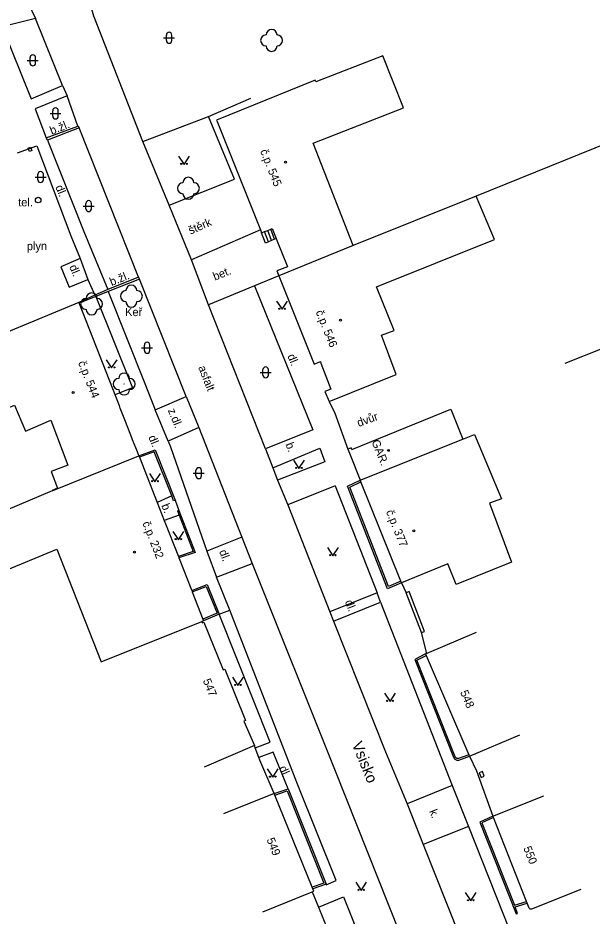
# Model space of a CAD drawing. Extents: x -577457 to -568404, y -1208466 to -1201387.
# Drawn here: x -575093.5 to -575041.2, y -1204524.1 to -1204442.2 of the extents above; entities that cross this region are included whole.
import ezdxf

# ---------------------------------------------------------------- set-up
doc = ezdxf.new("R2010")
doc.units = 0
for name, color, linetype in [('BUDOVY_MĚŘ', 7, 'Continuous'), ('BUDOVY_NEMĚŘ', 7, 'Continuous'), ('NÁZVY_ULIC_TOK_SMĚR', 7, 'Continuous'), ('OBVOD_PILÍŘE', 7, 'Continuous'), ('POMOC_POPIS', 7, 'Continuous'), ('ROZHRANÍ_PLOCH', 7, 'Continuous'), ('ZELEŇ', 7, 'Continuous'), ('ZN_BUDOV', 7, 'Continuous'), ('ZN_DOPLŇKOVÉ', 7, 'Continuous'), ('ZN_KULTUR', 7, 'Continuous'), ('Č_POPIS_ORIENT', 7, 'Continuous')]:
    doc.layers.add(name, color=color, linetype=linetype)

msp = doc.modelspace()

# ---------------------------------------------------------------- linework, layer by layer
at = {"layer": 'BUDOVY_MĚŘ'}
for points in [[(-575075.44, -1204451.53), (-575075.38, -1204451.68)], [(-575075.38, -1204451.68), (-575071.43, -1204461.55), (-575071.36, -1204461.73)], [(-575071.36, -1204461.73), (-575071.33, -1204461.81)], [(-575071.33, -1204461.81), (-575071.05, -1204461.7)], [(-575071.05, -1204461.7), (-575070.77, -1204461.59)], [(-575070.77, -1204461.59), (-575070.5, -1204461.48)], [(-575070.5, -1204461.48), (-575070.37, -1204461.43)], [(-575070.01, -1204462.33), (-575069.91, -1204462.58)], [(-575068.99, -1204464.84), (-575068.96, -1204464.92), (-575069.93, -1204465.28), (-575069.76, -1204465.75)], [(-575069.76, -1204465.75), (-575069.71, -1204465.88)], [(-575069.71, -1204465.88), (-575066.65, -1204473.49)], [(-575087.98, -1204468.17), (-575087.95, -1204468.25)], [(-575087.95, -1204468.25), (-575084.33, -1204477.56)], [(-575066.65, -1204473.49), (-575066.59, -1204473.63)], [(-575066.59, -1204473.63), (-575066.53, -1204473.79), (-575065.97, -1204473.56), (-575065.92, -1204473.7)], [(-575065.61, -1204474.49), (-575065, -1204476.06), (-575065.55, -1204476.29), (-575065.18, -1204477.2)], [(-575084.33, -1204477.56), (-575084.27, -1204477.72)], [(-575084.27, -1204477.72), (-575084.25, -1204477.77)], [(-575083.77, -1204479), (-575083.18, -1204480.49)], [(-575083.18, -1204480.49), (-575083.12, -1204480.65)], [(-575083.12, -1204480.65), (-575082.67, -1204481.77)], [(-575063.1, -1204481.56), (-575063.15, -1204481.42), (-575063.47, -1204481.53)], [(-575063.47, -1204481.53), (-575063.26, -1204482.05)], [(-575082.67, -1204481.77), (-575082.61, -1204481.93)], [(-575082.61, -1204481.93), (-575082.52, -1204482.15)], [(-575082.52, -1204482.15), (-575082.47, -1204482.28)], [(-575082.47, -1204482.28), (-575080.85, -1204486.39)], [(-575062.37, -1204484.27), (-575062.33, -1204484.37)], [(-575062.27, -1204484.51), (-575062.33, -1204484.37)], [(-575058.62, -1204493.57), (-575062.27, -1204484.51)], [(-575080.85, -1204486.39), (-575080.2, -1204488.04)], [(-575080.2, -1204488.04), (-575078.91, -1204491.33)], [(-575078.91, -1204491.33), (-575078.86, -1204491.46)], [(-575078.86, -1204491.46), (-575078.79, -1204491.65)], [(-575058.56, -1204493.72), (-575058.62, -1204493.57)], [(-575077.78, -1204494.23), (-575077.7, -1204494.42)], [(-575077.7, -1204494.42), (-575077.65, -1204494.56)], [(-575077.65, -1204494.56), (-575076.68, -1204497.04)], [(-575076.68, -1204497.04), (-575076.62, -1204497.18)], [(-575076.62, -1204497.18), (-575076.79, -1204497.25)], [(-575076.79, -1204497.25), (-575076.74, -1204497.38), (-575076.6, -1204497.32), (-575074.83, -1204501.65), (-575074.69, -1204501.6), (-575072.8, -1204506.27), (-575072.94, -1204506.33), (-575071.98, -1204508.57)], [(-575051.77, -1204498.25), (-575056.25, -1204500.16)], [(-575056.25, -1204500.16), (-575056.37, -1204500.21)], [(-575056.37, -1204500.21), (-575056.31, -1204500.35)], [(-575056.31, -1204500.35), (-575052.44, -1204509.4)], [(-575052.38, -1204509.54), (-575047.79, -1204507.58)], [(-575071.98, -1204508.57), (-575076.58, -1204510.54)], [(-575052.44, -1204509.4), (-575052.38, -1204509.54)], [(-575070.17, -1204512.93), (-575074.81, -1204514.8)], [(-575070.11, -1204513.08), (-575070.17, -1204512.93)], [(-575066.72, -1204521.48), (-575070.11, -1204513.08)], [(-575050.24, -1204515), (-575045.59, -1204513.16)], [(-575050.18, -1204515.14), (-575050.24, -1204515)], [(-575047.17, -1204522.79), (-575050.18, -1204515.14)], [(-575066.66, -1204521.63), (-575066.72, -1204521.48)], [(-575066.72, -1204521.91), (-575066.57, -1204521.85), (-575066.66, -1204521.63)], [(-575042.22, -1204521.7), (-575046.73, -1204523.48), (-575046.84, -1204523.48), (-575046.93, -1204523.4), (-575047.11, -1204522.93)], [(-575071.21, -1204523.72), (-575066.72, -1204521.91)], [(-575047.11, -1204522.93), (-575047.17, -1204522.79)]]:
    msp.add_lwpolyline(points, dxfattribs=at)
at = {"layer": 'BUDOVY_NEMĚŘ'}
for points in [[(-575062.99, -1204462.97), (-575066.63, -1204453.64), (-575058.38, -1204450.42), (-575060.28, -1204445.68), (-575066.38, -1204448.06), (-575066.44, -1204447.91), (-575075.44, -1204451.53)], [(-575065.18, -1204477.2), (-575059.05, -1204474.73), (-575060.4, -1204471.16), (-575059.24, -1204470.72), (-575060.84, -1204466.73), (-575050.1, -1204462.42), (-575051.77, -1204458.47), (-575062.99, -1204462.97), (-575069.76, -1204465.75)], [(-575087.98, -1204468.17), (-575098.86, -1204472.68), (-575102.69, -1204474.2), (-575109.74, -1204477.23), (-575108, -1204481.48), (-575098.52, -1204477.5), (-575097.81, -1204479.2), (-575093.85, -1204477.52), (-575092.85, -1204479.89), (-575090.54, -1204478.91), (-575089.01, -1204483), (-575090.52, -1204483.58), (-575089.95, -1204485.11), (-575090.43, -1204485.3), (-575090.41, -1204485.35), (-575082.52, -1204482.15)], [(-575063.1, -1204481.56), (-575054.08, -1204477.88), (-575052.98, -1204480.63)], [(-575062.33, -1204484.37), (-575052.98, -1204480.63), (-575051.9, -1204480.2), (-575049.46, -1204486.06), (-575050.56, -1204486.47), (-575048.55, -1204491.85), (-575053.58, -1204493.88), (-575054.34, -1204492.01), (-575058.56, -1204493.72)], [(-575090.41, -1204485.35), (-575099.9, -1204489.34), (-575103.91, -1204491.03), (-575109.16, -1204493.23), (-575107.19, -1204497.79), (-575098.59, -1204494.23), (-575089.99, -1204490.66), (-575085.95, -1204500.94), (-575076.79, -1204497.25)]]:
    msp.add_lwpolyline(points, dxfattribs=at)
at = {"layer": 'OBVOD_PILÍŘE'}
msp.add_lwpolyline([(-575092.34, -1204454.17), (-575092.28, -1204454.32), (-575092.49, -1204454.4), (-575092.6, -1204454.1), (-575092.4, -1204454.02), (-575092.34, -1204454.17)], dxfattribs=at)
at = {"layer": 'ROZHRANÍ_PLOCH'}
for points in [[(-575082.17, -1204453.5), (-575086.64, -1204442.06), (-575086.9, -1204441.13), (-575085.27, -1204440.74), (-575085.33, -1204439.77), (-575085.22, -1204438.76), (-575085.08, -1204438.35), (-575084.56, -1204437.58), (-575084.14, -1204437.25), (-575083.73, -1204436.91), (-575082.75, -1204436.68), (-575075.88, -1204435.68), (-575075.55, -1204437.94), (-575072.53, -1204437.47)], [(-575093.33, -1204439.52), (-575092.57, -1204440.95), (-575091.95, -1204442.28)], [(-575091.95, -1204442.28), (-575094.97, -1204443.02), (-575092.34, -1204449.59), (-575089.47, -1204448.38)], [(-575089.47, -1204448.38), (-575091.95, -1204442.28)], [(-575089.47, -1204448.38), (-575089.06, -1204449.34)], [(-575089.06, -1204449.34), (-575091.97, -1204450.51), (-575090.98, -1204453.17)], [(-575088.08, -1204452.08), (-575089.06, -1204449.34)], [(-575079.76, -1204459.29), (-575073.79, -1204456.93), (-575076.18, -1204451.2), (-575072.3, -1204449.55)], [(-575082.54, -1204465.87), (-575087.97, -1204452.25)], [(-575090.84, -1204453.37), (-575087.55, -1204461.69), (-575085.35, -1204466.97)], [(-575079.76, -1204459.29), (-575082.17, -1204453.5)], [(-575093.58, -1204454.52), (-575091.83, -1204453.89), (-575088.73, -1204462.08), (-575087.88, -1204464.15), (-575089.62, -1204464.93), (-575088.87, -1204466.77), (-575087.18, -1204466.07), (-575086.54, -1204467.49)], [(-575071.43, -1204461.55), (-575077.71, -1204464.27), (-575079.76, -1204459.29)], [(-575070.7, -1204462.63), (-575070.98, -1204462.75), (-575071.33, -1204461.81)], [(-575070.7, -1204462.63), (-575071.05, -1204461.7)], [(-575070.43, -1204462.51), (-575070.77, -1204461.59)], [(-575070.15, -1204462.39), (-575070.5, -1204461.48)], [(-575070.43, -1204462.51), (-575070.7, -1204462.63)], [(-575070.15, -1204462.39), (-575070.43, -1204462.51)], [(-575070.01, -1204462.33), (-575070.15, -1204462.39)], [(-575087.88, -1204464.15), (-575087.18, -1204466.07)], [(-575076.16, -1204468.38), (-575077.71, -1204464.27)], [(-575078.22, -1204476.75), (-575082.45, -1204466.03)], [(-575071.97, -1204466.66), (-575076.16, -1204468.38)], [(-575071.97, -1204466.66), (-575066.66, -1204479.77), (-575070.97, -1204481.5)], [(-575086.43, -1204467.61), (-575083.1, -1204475.96), (-575084.7, -1204476.59)], [(-575085.33, -1204467.17), (-575081.96, -1204475.54), (-575081.03, -1204477.95), (-575078.22, -1204476.75)], [(-575070.97, -1204481.5), (-575076.16, -1204468.38)], [(-575078.22, -1204476.75), (-575077.06, -1204479.57)], [(-575079.85, -1204480.81), (-575081.03, -1204477.95)], [(-575077.06, -1204479.57), (-575079.85, -1204480.81), (-575079.63, -1204481.33)], [(-575077.06, -1204479.57), (-575073.13, -1204489.58)], [(-575079.63, -1204481.33), (-575076.31, -1204490.85)], [(-575070.97, -1204481.5), (-575070.31, -1204483.23)], [(-575070.31, -1204483.23), (-575066.01, -1204481.45), (-575065.56, -1204482.69)], [(-575065.56, -1204482.69), (-575069.88, -1204484.36)], [(-575070.31, -1204483.23), (-575069.88, -1204484.36)], [(-575069.88, -1204484.36), (-575068.95, -1204486.61)], [(-575064.61, -1204484.88), (-575068.95, -1204486.61)], [(-575064.61, -1204484.88), (-575060.79, -1204494.65)], [(-575079.52, -1204485.8), (-575080.85, -1204486.39)], [(-575068.95, -1204486.61), (-575065.1, -1204496.36)], [(-575078.85, -1204487.55), (-575080.2, -1204488.04)], [(-575073.13, -1204489.58), (-575076.31, -1204490.85)], [(-575073.13, -1204489.58), (-575072.18, -1204491.97)], [(-575076.31, -1204490.85), (-575075.44, -1204493.21)], [(-575075.44, -1204493.21), (-575072.18, -1204491.97)], [(-575072.18, -1204491.97), (-575064.62, -1204510.86), (-575052.9, -1204540.39)], [(-575074.21, -1204496.22), (-575075.44, -1204493.21)], [(-575060.79, -1204494.65), (-575065.1, -1204496.36)], [(-575060.49, -1204495.49), (-575060.79, -1204494.65)], [(-575064.77, -1204497.21), (-575060.49, -1204495.49)], [(-575060.49, -1204495.49), (-575053.94, -1204512.22)], [(-575075.19, -1204496.58), (-575074.21, -1204496.22)], [(-575065.45, -1204521.21), (-575065.43, -1204521.27), (-575064.52, -1204520.86), (-575068.04, -1204512.1), (-575074.21, -1204496.22)], [(-575071.91, -1204508.76), (-575070.56, -1204508.25), (-575075.19, -1204496.58)], [(-575065.1, -1204496.36), (-575064.77, -1204497.21)], [(-575064.77, -1204497.21), (-575060.04, -1204509.13), (-575058.07, -1204513.88)], [(-575068.9, -1204512.51), (-575070.26, -1204509.18), (-575071.58, -1204509.66)], [(-575053.94, -1204512.22), (-575058.07, -1204513.88)], [(-575053.94, -1204512.22), (-575052.47, -1204515.95)], [(-575058.07, -1204513.88), (-575056.59, -1204517.59)], [(-575052.47, -1204515.95), (-575056.59, -1204517.59)], [(-575052.47, -1204515.95), (-575048.12, -1204526.92)], [(-575056.59, -1204517.59), (-575052.21, -1204528.58)], [(-575066.15, -1204523.31), (-575063.85, -1204522.37), (-575058.31, -1204536.3), (-575058.02, -1204536.17), (-575055.71, -1204541.56), (-575056.12, -1204541.74), (-575055.95, -1204542.22)]]:
    msp.add_lwpolyline(points, dxfattribs=at)
at = {"layer": 'ZELEŇ'}
msp.add_lwpolyline([(-575082.17, -1204453.5), (-575076.18, -1204451.2)], dxfattribs=at)
for centre in [(-575070.42, -1204444.27), (-575078, -1204457.75), (-575083.2, -1204467.59), (-575086.83, -1204468.3), (-575083.86, -1204475.6)]:
    msp.add_circle(centre, 0.0005, dxfattribs=at)
for centre, start, end in [((-575070.92, -1204444.27), 89.99999, 269.99999), ((-575070.42, -1204443.77), 0, 179.99999), ((-575069.92, -1204444.27), 270, 89.99999), ((-575070.42, -1204444.77), 179.99999, 359.99999), ((-575078, -1204457.25), 0, 179.99999), ((-575078.5, -1204457.75), 89.99999, 269.99999), ((-575077.5, -1204457.75), 270, 89.99999), ((-575078, -1204458.25), 179.99999, 359.99999), ((-575083.2, -1204467.09), 0, 179.99999), ((-575086.83, -1204467.8), 0, 179.99999), ((-575083.7, -1204467.59), 89.99999, 269.99999), ((-575082.7, -1204467.59), 270, 89.99999), ((-575087.33, -1204468.3), 89.99999, 269.99999), ((-575086.33, -1204468.3), 270, 89.99999), ((-575083.2, -1204468.09), 179.99999, 359.99999), ((-575086.83, -1204468.8), 179.99999, 359.99999), ((-575083.86, -1204475.1), 0, 179.99999), ((-575084.36, -1204475.6), 89.99999, 269.99999), ((-575083.36, -1204475.6), 270, 89.99999), ((-575083.86, -1204476.1), 179.99999, 359.99999)]:
    msp.add_arc(centre, 0.5, start, end, dxfattribs=at)
at = {"layer": 'ZN_BUDOV'}
for centre in [(-575069.16, -1204455.38), (-575064.13, -1204469.77), (-575088.5, -1204476.38), (-575059.77, -1204481.65), (-575057.45, -1204488.98), (-575082.93, -1204490.94)]:
    msp.add_circle(centre, 0.0875, dxfattribs=at)
at = {"layer": 'ZN_DOPLŇKOVÉ'}
for points in [[(-575014.05, -1204443.22), (-575051.77, -1204458.47)], [(-575090.98, -1204453.17), (-575088.08, -1204452.08), (-575087.97, -1204452.25), (-575090.84, -1204453.37), (-575090.98, -1204453.17)], [(-575007.73, -1204459.47), (-575043.68, -1204473.72)], [(-575070.37, -1204461.43), (-575070.01, -1204462.33)], [(-575069.91, -1204462.58), (-575068.99, -1204464.84)], [(-575082.54, -1204465.87), (-575085.35, -1204466.97), (-575086.54, -1204467.49), (-575087.98, -1204468.17)], [(-575082.54, -1204465.87), (-575082.45, -1204466.03), (-575085.33, -1204467.17), (-575086.43, -1204467.61), (-575087.52, -1204468.06), (-575087.95, -1204468.25)], [(-575069.76, -1204465.75), (-575071.97, -1204466.66)], [(-575065.92, -1204473.7), (-575065.61, -1204474.49)], [(-575065.18, -1204477.2), (-575064.64, -1204478.27), (-575063.47, -1204481.53)], [(-575084.25, -1204477.77), (-575083.77, -1204479)], [(-575082.52, -1204482.15), (-575081.04, -1204481.61), (-575079.22, -1204486.19)], [(-575079.52, -1204485.8), (-575081.12, -1204481.79), (-575082.47, -1204482.28)], [(-575063.26, -1204482.05), (-575062.37, -1204484.27)], [(-575058.56, -1204493.72), (-575059.86, -1204494.27), (-575063.5, -1204484.93), (-575062.33, -1204484.37)], [(-575058.62, -1204493.57), (-575059.77, -1204494.06), (-575063.29, -1204485.01), (-575062.27, -1204484.51)], [(-575079.22, -1204486.19), (-575079.35, -1204486.24), (-575079.52, -1204485.8)], [(-575079.22, -1204486.19), (-575078.86, -1204487.13)], [(-575078.86, -1204487.13), (-575078.99, -1204487.18), (-575078.85, -1204487.55)], [(-575078.86, -1204487.13), (-575077.39, -1204490.95), (-575078.86, -1204491.46)], [(-575078.85, -1204487.55), (-575077.57, -1204490.87), (-575078.91, -1204491.33)], [(-575078.79, -1204491.65), (-575077.78, -1204494.23)], [(-575058.56, -1204493.72), (-575058.16, -1204494.63)], [(-575077.7, -1204494.42), (-575076.29, -1204493.87), (-575075.19, -1204496.58)], [(-575077.65, -1204494.56), (-575076.37, -1204494.06), (-575075.39, -1204496.5), (-575076.68, -1204497.04)], [(-575056.75, -1204498.26), (-575056.47, -1204498.16), (-575057.88, -1204494.52), (-575058.16, -1204494.63)], [(-575056.75, -1204498.26), (-575058.16, -1204494.63)], [(-575075.19, -1204496.58), (-575076.62, -1204497.18)], [(-575056.25, -1204500.16), (-575056.75, -1204498.26)], [(-575056.37, -1204500.21), (-575057.35, -1204500.71), (-575053.83, -1204509.63), (-575053.7, -1204509.8), (-575053.53, -1204509.89), (-575053.34, -1204509.91), (-575052.38, -1204509.54)], [(-575052.44, -1204509.4), (-575053.37, -1204509.76), (-575053.53, -1204509.74), (-575053.65, -1204509.64), (-575053.69, -1204509.58), (-575057.16, -1204500.78), (-575056.31, -1204500.35)], [(-575071.91, -1204508.76), (-575071.98, -1204508.57)], [(-575071.58, -1204509.66), (-575071.91, -1204508.76)], [(-575070.17, -1204512.93), (-575071.49, -1204509.9), (-575071.58, -1204509.66)], [(-575052.38, -1204509.54), (-575051.74, -1204510.87)], [(-575051.74, -1204510.87), (-575050.24, -1204515)], [(-575051.48, -1204511.06), (-575051.31, -1204511.47), (-575051.02, -1204511.35), (-575051.2, -1204510.94), (-575051.48, -1204511.06)], [(-575070.17, -1204512.93), (-575068.9, -1204512.51)], [(-575068.9, -1204512.51), (-575065.45, -1204521.21)], [(-575070.11, -1204513.08), (-575069, -1204512.71), (-575065.66, -1204521.12), (-575066.72, -1204521.48)], [(-575050.24, -1204515), (-575051.44, -1204515.54), (-575048.12, -1204523.92), (-575047.98, -1204523.87), (-575048.22, -1204523.27), (-575047.11, -1204522.93)], [(-575050.18, -1204515.14), (-575051.25, -1204515.62), (-575048.27, -1204523.13), (-575047.17, -1204522.79)], [(-575065.45, -1204521.21), (-575066.66, -1204521.63)], [(-575066.72, -1204521.91), (-575066.15, -1204523.31)], [(-575066.15, -1204523.31), (-575064.95, -1204526.22)]]:
    msp.add_lwpolyline(points, dxfattribs=at)
for radius in [0.25, 0.0005]:
    msp.add_circle((-575091.7, -1204458.83), radius, dxfattribs=at)
at = {"layer": 'ZN_KULTUR'}
for p, q in [((-575080.01, -1204444.28), (-575080.01, -1204443.78)), ((-575079.51, -1204444.28), (-575079.51, -1204443.78)), ((-575080.26, -1204444.03), (-575079.26, -1204444.03)), ((-575092.69, -1204446.09), (-575091.69, -1204446.09)), ((-575092.44, -1204446.34), (-575092.44, -1204445.84)), ((-575091.94, -1204446.34), (-575091.94, -1204445.84)), ((-575090.62, -1204450.93), (-575089.62, -1204450.93)), ((-575090.37, -1204451.18), (-575090.37, -1204450.68)), ((-575089.87, -1204451.18), (-575089.87, -1204450.68)), ((-575091.98, -1204456.73), (-575090.98, -1204456.73)), ((-575091.73, -1204456.98), (-575091.73, -1204456.48)), ((-575091.23, -1204456.98), (-575091.23, -1204456.48)), ((-575087.6, -1204459.38), (-575086.6, -1204459.38)), ((-575087.35, -1204459.63), (-575087.35, -1204459.13)), ((-575086.85, -1204459.63), (-575086.85, -1204459.13)), ((-575082.27, -1204472.3), (-575081.27, -1204472.3)), ((-575082.02, -1204472.55), (-575082.02, -1204472.05)), ((-575081.52, -1204472.55), (-575081.52, -1204472.05)), ((-575071.46, -1204474.54), (-575070.46, -1204474.54)), ((-575071.21, -1204474.79), (-575071.21, -1204474.29)), ((-575070.71, -1204474.79), (-575070.71, -1204474.29)), ((-575077.56, -1204483.73), (-575076.56, -1204483.73)), ((-575077.31, -1204483.98), (-575077.31, -1204483.48)), ((-575076.81, -1204483.98), (-575076.81, -1204483.48))]:
    msp.add_line(p, q, dxfattribs=at)
for points in [[(-575078.9, -1204454.83), (-575078.4, -1204455.58), (-575077.9, -1204454.83)], [(-575069.96, -1204468.04), (-575069.46, -1204468.79), (-575068.96, -1204468.04)], [(-575085.5, -1204473.39), (-575085, -1204474.14), (-575084.5, -1204473.39)], [(-575068.42, -1204482.55), (-575067.92, -1204483.3), (-575067.42, -1204482.55)], [(-575081.55, -1204483.76), (-575081.05, -1204484.51), (-575080.55, -1204483.76)], [(-575079.41, -1204489.05), (-575078.91, -1204489.8), (-575078.41, -1204489.05)], [(-575065.33, -1204490.51), (-575064.83, -1204491.26), (-575064.33, -1204490.51)], [(-575073.99, -1204502.34), (-575073.49, -1204503.09), (-575072.99, -1204502.34)], [(-575060.12, -1204503.79), (-575059.62, -1204504.54), (-575059.12, -1204503.79)], [(-575070.81, -1204510.7), (-575070.31, -1204511.45), (-575069.81, -1204510.7)], [(-575062.75, -1204521.02), (-575062.25, -1204521.77), (-575061.75, -1204521.02)], [(-575052.76, -1204521.97), (-575052.26, -1204522.72), (-575051.76, -1204521.97)]]:
    msp.add_lwpolyline(points, dxfattribs=at)
for centre in [(-575078.65, -1204455.53), (-575078.15, -1204455.53), (-575069.71, -1204468.74), (-575069.21, -1204468.74), (-575085.25, -1204474.09), (-575084.75, -1204474.09), (-575068.17, -1204483.25), (-575067.67, -1204483.25), (-575081.3, -1204484.46), (-575080.8, -1204484.46), (-575079.16, -1204489.75), (-575078.66, -1204489.75), (-575065.08, -1204491.21), (-575064.58, -1204491.21), (-575073.74, -1204503.04), (-575073.24, -1204503.04), (-575059.87, -1204504.49), (-575059.37, -1204504.49), (-575070.56, -1204511.4), (-575070.06, -1204511.4), (-575062.5, -1204521.72), (-575062, -1204521.72), (-575052.51, -1204522.67), (-575052.01, -1204522.67)]:
    msp.add_circle(centre, 0.05, dxfattribs=at)
for centre, start, end in [((-575079.76, -1204443.78), 0, 179.99999), ((-575079.76, -1204444.28), 179.99999, 359.99999), ((-575092.19, -1204445.84), 0, 179.99999), ((-575092.19, -1204446.34), 179.99999, 359.99999), ((-575090.12, -1204450.68), 0, 179.99999), ((-575090.12, -1204451.18), 179.99999, 359.99999), ((-575091.48, -1204456.48), 0, 179.99999), ((-575091.48, -1204456.98), 179.99999, 359.99999), ((-575087.1, -1204459.13), 0, 179.99999), ((-575087.1, -1204459.63), 179.99999, 359.99999), ((-575081.77, -1204472.05), 0, 179.99999), ((-575081.77, -1204472.55), 179.99999, 359.99999), ((-575070.96, -1204474.29), 0, 179.99999), ((-575070.96, -1204474.79), 179.99999, 359.99999), ((-575077.06, -1204483.48), 0, 179.99999), ((-575077.06, -1204483.98), 179.99999, 359.99999)]:
    msp.add_arc(centre, 0.25, start, end, dxfattribs=at)

# ---------------------------------------------------------------- texts
at = {"layer": 'NÁZVY_ULIC_TOK_SMĚR'}
msp.add_text('Vsisko', height=1, rotation=292.18, dxfattribs=at).set_placement((-575063.12, -1204508.44))
at = {"layer": 'POMOC_POPIS'}
for s, rotation, p in [('b.žl.', 21.31793, (-575090.47, -1204452.88)), ('dl.', 292.08042, (-575090.15, -1204457.63)), ('tel.', 0.27416, (-575093.52, -1204459.4)), ('štěrk', 23.39559, (-575077.81, -1204461.98)), ('plyn', 0.30453, (-575092.73, -1204463.4)), ('dl.', 292.36312, (-575088.88, -1204464.9)), ('bet.', 21.79113, (-575075.59, -1204466.18)), ('b.žl.', 21.59529, (-575085.01, -1204466.67)), ('dl.', 292.35, (-575068.99, -1204473.04)), ('asfalt', 291.73613, (-575077.13, -1204474.09)), ('z.dl.', 292.08042, (-575079.89, -1204477.99)), ('dvůr', 19.88519, (-575062.47, -1204479.52)), ('dl.', 292.08042, (-575081.67, -1204480.44)), ('GAR.', 291.89003, (-575061.32, -1204480.85)), ('b.', 290.79, (-575069.16, -1204481.09)), ('b.', 291.44002, (-575080.48, -1204486.67)), ('dl.', 290.13001, (-575075.21, -1204490.86)), ('dl.', 290.79, (-575063.74, -1204495.44)), ('dl.', 293.64001, (-575069.76, -1204510.6)), ('k.', 291.80998, (-575056.06, -1204514.55))]:
    msp.add_text(s, height=0.75, rotation=rotation, dxfattribs=at).set_placement(p)
at = {"layer": 'ZELEŇ'}
msp.add_text('Keř', height=0.75, dxfattribs=at).set_placement((-575083.77, -1204469.41))
at = {"layer": 'Č_POPIS_ORIENT'}
for s, rotation, p in [('č.p. 545', 291.80139, (-575071.48, -1204454.36)), ('č.p. 546', 291.90521, (-575066.41, -1204469.03)), ('č.p. 544', 291.55639, (-575088.08, -1204473.65)), ('č.p. 377', 291.94302, (-575060, -1204487.24)), ('č.p. 232', 291.41, (-575082.21, -1204488.28)), ('547', 292.01, (-575076.7, -1204502.64)), ('548', 293.1, (-575053.24, -1204503.7)), ('549', 291.95001, (-575070.89, -1204517.14)), ('550', 291.50998, (-575047.48, -1204517.91))]:
    msp.add_text(s, height=0.75, rotation=rotation, dxfattribs=at).set_placement(p)

doc.saveas('drawing.dxf')
